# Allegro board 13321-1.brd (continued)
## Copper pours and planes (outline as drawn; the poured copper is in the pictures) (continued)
HDMI_PLL_GND on TOP: 16.76,74.9 16.64,75.02 16.64,75.41 16.76,75.53 17.4,75.53 18.44,76.57 18.44,83.46 18.52,83.53 19.18,83.53 19.56,83.15 19.56,75.15 19.3,74.9
HSIO_OUT on BOTTOM: 58.42,71.34 58.17,71.6 58.17,72.61 58.67,73.12 58.67,74.64 58.8,74.77 60.07,74.77 60.2,74.64 60.2,71.6 59.94,71.34
KB_BL_CTRL# on BOTTOM: 24.13,8.98 24,9.11 24,9.75 23.88,9.87 23.88,12.29 23.5,12.67 23.5,13.05 23.62,13.18 24.13,13.18 24.77,12.54 24.77,9.87 25.02,9.62 25.02,9.11 24.89,8.98
LCDVDD on TOP: 46.23,95.47 45.97,95.73 45.97,98.77 46.1,98.9 51.05,98.9 51.18,98.77 51.18,97.5 51.05,97.38 48.51,97.38 48.01,96.87 48.01,95.73 47.75,95.47 ; 4 cut-outs
LCDVDD on BOTTOM: 46.89,93.39 46.89,94.81 46.61,95.09 46.23,95.09 46.1,95.22 46.1,95.98 46.35,96.23 48.01,96.23 48.13,96.11 48.13,95.47 47.7,95.04 47.7,93.41 47.68,93.39 47.4,93.39 47.4,94.71 47.35,94.76 47.24,94.76 47.19,94.71 47.19,93.39
M_VREF_CA_DIMMA on TOP: 137.29,65.25 135.38,67.15 135.38,70.58 132.08,73.88 130.05,73.88 129.92,74.01 129.92,74.52 130.05,74.64 130.05,75.53 130.18,75.66 133.86,75.66 134.11,75.41 134.11,73.5 136.53,71.09 136.53,67.91 138.05,66.39 138.05,65.37 137.92,65.25 ; 4 cut-outs
M_VREF_CA_DIMMA on BOTTOM: 137.67,65.12 137.41,65.37 137.41,66.52 137.54,66.64 139.45,66.64 139.57,66.52 139.57,65.25 139.45,65.12 ; 2 cut-outs
M_VREF_DQ_DIMMA on TOP: 121.03,32.99 120.9,33.11 120.9,34.38 121.03,34.51 125.48,34.51 125.73,34.26 125.73,33.37 125.35,32.99 ; 6 cut-outs
PWR_1D35V on BOTTOM: 137.16,50.77 135.89,52.04 135.89,53.43 136.02,53.56 136.02,56.86 136.14,56.99 142.24,56.99 142.37,56.86 142.37,51.53 141.6,50.77 ; 2 cut-outs
PWR_1D35V_PHASE on BOTTOM: 139.06,44.93 139.06,46.07 138.56,46.58 138.56,48.86 138.68,48.99 140.72,48.99 140.84,48.86 140.84,46.7 140.34,46.2 140.34,44.93
PWR_3D3V_LL2 on BOTTOM: 35.05,75.91 34.8,76.17 34.8,79.85 35.05,80.1 39.24,80.1 39.37,79.98 39.37,76.93 39.24,76.8 38.1,76.8 37.72,76.42 37.72,76.04 37.59,75.91
PWR_5V_LL1 on BOTTOM: 26.8,75.91 26.54,76.17 26.54,79.72 26.8,79.98 30.1,79.98 30.23,79.85 30.23,76.42 29.72,75.91
PWR_CHG_PHASE on BOTTOM: 57.53,23.84 56.26,25.11 56.26,26.13 55.88,26.51 50.55,26.51 50.55,29.43 55.75,29.43 57.15,30.83 60.2,30.83 61.47,29.56 61.47,24.22 61.09,23.84
PWR_DCBATOUT_1D35V on BOTTOM: 139.45,39.46 139.32,39.59 139.32,42 139.06,42.26 139.06,43.78 141.1,43.78 141.48,43.4 141.48,43.02 141.6,42.89 142.37,42.89 142.88,42.39 144.27,42.39 144.4,42.26 144.4,41.24 142.62,39.46 ; 2 cut-outs
PWR_VCC_VSW1 on BOTTOM: 48.26,63.21 48.01,63.47 48.01,66.9 48.77,67.66 48.77,69.06 48.9,69.18 49.66,69.18 50.04,69.56 50.04,71.34 50.16,71.47 52.32,71.47 52.32,69.69 53.09,68.93 53.09,63.59 52.7,63.21
RING2 on BOTTOM: 16.89,21.94 16.76,22.07 16.76,23.97 17.65,24.86 17.65,28.29 17.78,28.42 18.67,28.42 18.92,28.16 18.92,24.22 18.03,23.34 18.03,22.07 17.91,21.94 ; 2 cut-outs
SLEEVE on TOP: 18.54,33.24 18.41,33.37 18.41,34 18.29,34.13 18.29,35.15 18.41,35.27 19.05,35.27 19.3,35.02 19.3,34.26 19.43,34.13 20.07,34.13 20.19,34 20.19,33.37 20.07,33.24 ; 1 cut-out
TP_VDD on TOP: 117.22,25.11 117.09,25.24 117.09,26.64 116.71,27.02 112.39,27.02 112.27,27.15 112.27,28.03 112.01,28.29 112.01,29.05 112.14,29.18 113.16,29.18 113.28,29.05 116.84,29.05 118.49,27.4 118.49,25.24 118.36,25.11 ; 3 cut-outs
TP_VDD on BOTTOM: 109.86,21.05 106.93,23.97 104.78,23.97 104.65,24.1 104.65,25.49 104.9,25.75 107.44,25.75 107.82,25.37 107.82,25.24 110.74,22.32 116.2,22.32 116.46,22.57 116.46,22.95 116.97,23.46 116.97,25.49 117.22,25.75 118.24,25.75 119.25,24.73 119.25,22.07 118.24,21.05 ; 2 cut-outs
TPAN_VDD on TOP: 28.96,94.71 28.83,94.84 28.83,95.85 29.08,96.11 30.48,96.11 32.26,97.88 32.26,99.92 32.38,100.04 34.04,100.04 34.16,99.92 34.16,96.36 33.91,96.11 32,96.11 31.75,95.85 31.75,94.84 31.62,94.71 ; 1 cut-out
TPAN_VDD on BOTTOM: 28.19,94.71 28.07,94.84 28.07,96.49 28.57,97 30.15,97 30.73,96.41 31.75,96.41 31.75,96.08 30.78,96.08 30.58,95.88 30.58,95.07 30.23,94.71
USB30_VCCA on BOTTOM: 26.16,55.47 26.16,59.4 24.77,60.8 24.77,64.99 24,65.75 14.73,65.75 14.22,66.26 14.22,67.4 14.61,67.79 25.27,67.79 27.05,66.01 27.05,61.69 28.32,60.42 28.32,56.23 27.56,55.47 ; 4 cut-outs
USB30_VCCB on BOTTOM: 20.07,47.21 19.56,47.72 15.88,47.72 15.37,48.23 15.37,49.88 15.75,50.26 21.46,50.26 22.48,49.24 24.38,49.24 24.38,47.97 24.26,47.85 22.73,47.85 22.1,47.21 ; 4 cut-outs

Small or netless copper shapes (teardrops, artwork), in the pictures only: 2 on TOP, 1 on BOTTOM

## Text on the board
Ref Des/Silkscreen Bottom: X1801:24MHZ | F6201:.5A/6V | F5204:1.1A/6V | F5202:.5A/6V | X1901:32.768KHZ
User.Comments: IVY_0913 | SAMPINTO | BAKAKAY
Ref Des/Silkscreen Top: F5203:1.1A/24V | F5401:1.1A/6V | F5201:1.1A/24V | X6601:12MHZ | PWR:8X6G1 | Cottonwood MB | 13321-1 | REV:A00 | MADE IN TAIWAN
User.27: Board Accuracy Check,Jun 11 16:07:18 2014,Passed | Dummy-Static-No Shape On Layer Check,Jun 11 16:07:19 2014,Passed | Split Plane Check,Mar 06 15:28:04 2014,Passed | TP Violations Check,Oct 23 11:41:53 2013,729 errors | Via On Moat Check,Oct 21 14:33:23 2013,117 errors
User.28: HEADER:Board Accuracy Check:1=show;2=show;3=show | HEADER:Dummy-Static-No Shape On Layer Check:1=show;2=hide;3=show;4=hide;5=show;6=show;7=show | HEADER:Split Plane Check:1=show;2=hide;3=show;4=hide;5=show;6=show;7=show
User.30: ByImpedance:100.0@_REF_L1=("4.0/10.0(L1)")|_REF_L6=("4.0/10.0(L6)")|Type="DP"|_REF_L4=("4.0/9.0(L4)")|_REF_L3=("4.0/9.0(L3)")|imp="100.0" | ByImpedance:110.0@Type="DP"|_REF_L4=("3.5/13.0(L4)")|_REF_L3=("3.5/13.0(L3)")|imp="110.0" | ByImpedance:37.5@_REF_L1=("8.0(L1)")|_REF_L6=("8.0(L6)")|Type="SE"|_REF_L4=("9.5(L4)")|_REF_L3=("9.5(L3)")|imp="37.5" | ByImpedance:40.0@_REF_L1=("7.0(L1)")|_REF_L6=("7.0(L6)")|Type="SE"|_REF_L4=("8.0(L4)")|_REF_L3=("8.0(L3)")|imp="40.0" | ByImpedance:45.0@_REF_L1=("5.5(L1)")|_REF_L6=("5.5(L6)")|Type="SE"|_REF_L4=("6.5(L4)")|_REF_L3=("6.5(L3)")|imp="45.0" | ByImpedance:48.0@_REF_L1=("5.0(L1)")|_REF_L6=("5.0(L6)")|Type="SE"|_REF_L4=("6.0(L4)")|_REF_L3=("6.0(L3)")|imp="48.0" | ByImpedance:50.0@_REF_L1=("4.5(L1)")|_REF_L6=("4.5(L6)")|Type="SE"|_REF_L4=("5.0(L4)")|_REF_L3=("5.0(L3)")|imp="50.0" | ByImpedance:55.0@_REF_L1=("3.5(L1)")|_REF_L6=("3.5(L6)")|Type="SE"|_REF_L4=("4.0(L4)")|_REF_L3=("4.0(L3)")|imp="55.0" | ByImpedance:70.0@_REF_L1=("7.0/5.0(L1)")|_REF_L6=("7.0/5.0(L6)")|Type="DP"|_REF_L4=("8.0/5.0(L4)")|_REF_L3=("8.0/5.0(L3)")|imp="70.0" | ByImpedance:80.0@_REF_L1=("5.5/5.0(L1)")|_REF_L6=("5.5/5.0(L6)")|Type="DP"|_REF_L4=("5.5/5.0(L4)" "6.0/6.0(L4)" "5.0/4.0(L4)")|_REF_L3=("5.5/5.0(L3)" "6.0/6.0(L3)" "5.0/4.0(L3)")|imp="80.0" | ByImpedance:85.0@_REF_L1=("4.0/4.0(L1)" "5.0/6.0(L1)")|_REF_L6=("4.0/4.0(L6)" "5.0/6.0(L6)")|Type="DP"|_REF_L4=("5.5/7.0(L4)" "5.0/5.5(L4)" "4.5/4.5(L4)")|_REF_L3=("5.5/7.0(L3)" "5.0/5.5(L3)" "4.5/4.5(L3)")|imp="85.0" | ByImpedance:90.0@_REF_L1=("4.0/5.0(L1)")|_REF_L6=("4.0/5.0(L6)")|Type="DP"|_REF_L4=("5.0/8.0(L4)" "4.0/5.0(L4)" "4.5/6.0(L4)")|_REF_L3=("5.0/8.0(L3)" "4.0/5.0(L3)" "4.5/6.0(L3)")|imp="90.0" | ByImpedance:95.0@_REF_L1=("4.0/6.5(L1)")|_REF_L6=("4.0/6.5(L6)")|Type="DP"|_REF_L4=("4.0/6.5(L4)")|_REF_L3=("4.0/6.5(L3)")|imp="95.0" | LayerIndex:nil | Source:6-1.2-10.xls | artWorks:("_REF_L3" "_REF_L4" "_REF_L6" "_REF_L1") | gtImpOutlineUsed:BOARD GEOMETRY/PANEL_OUTLINE
User.31: 0 | 16 | 51 | 59 | 47 | 39 | 63 | 20
User.32: 8 | 118 | 126 | 181 | 161 | 59 | 49 | 79
User.33: AUD_AGND | 5V_S5 | 5V_S0 | GND | 3D3V_S0 | DCBATOUT | VCC_CORE | 1D05V_S0
User.34: AUD_AGND | GND
User.37: This gerber is just for your reference to find the DP impedance traces in layer L1. | DP IMPEDANCE TABLE: L1 | * - Denotes that WIDTH | is NOT used in this layer | inside board outline. | IMP(Ohm) | 70.0 | 80.0 | 85.0 | 90.0 | 95.0 | 100.0 | WIDTH(mils) | *7.0/5.0 | *5.5/5.0 | 4.0/4.0 | *5.0/6.0 | *4.0/5.0 | *4.0/6.5 | *4.0/10.0 | TYPE | DP
User.39: This gerber is just for your reference to find the SE impedance traces in layer L1. | SE IMPEDANCE TABLE: L1 | * - Denotes that WIDTH | is NOT used in this layer | inside board outline. | IMP(Ohm) | 37.5 | 40.0 | 45.0 | 48.0 | 50.0 | 55.0 | WIDTH(mils) | 8.0 | *7.0 | *5.5 | *5.0 | 4.5 | *3.5 | TYPE | SE
User.41: This gerber is just for your reference to find the DP impedance traces in layer L3. | DP IMPEDANCE TABLE: L3 | * - Denotes that WIDTH | is NOT used in this layer | inside board outline. | IMP(Ohm) | 70.0 | 80.0 | 85.0 | 90.0 | 95.0 | 100.0 | 110.0 | WIDTH(mils) | *8.0/5.0 | *5.5/5.0 | *6.0/6.0 | *5.0/4.0 | *5.5/7.0 | *5.0/5.5 | 4.5/4.5 | *5.0/8.0 | *4.0/5.0 | *4.5/6.0 | *4.0/6.5 | *4.0/9.0 | *3.5/13.0 | TYPE | DP
User.43: This gerber is just for your reference to find the SE impedance traces in layer L3. | SE IMPEDANCE TABLE: L3 | * - Denotes that WIDTH | is NOT used in this layer | inside board outline. | IMP(Ohm) | 37.5 | 40.0 | 45.0 | 48.0 | 50.0 | 55.0 | WIDTH(mils) | *9.5 | 8.0 | *6.5 | 6.0 | 5.0 | 4.0 | TYPE | SE
User.45: This gerber is just for you reference to find the differential traces in layer BOTTOM | This gerber is just for you reference to find the differential traces in layer L3 | This gerber is just for you reference to find the differential traces in layer L4 | This gerber is just for you reference to find the differential traces in layer TOP | Note:Refer to DRILL layer for ELLIPSE drill direction | FIGURE | SIZE | 10.0 | 16.0 | 20.0 | 28.0 | 32.0 | 40.0 | 125.0 | 178.0 | 229.0 | 38.0 | 44.0 | 63.0 | 86.0 | 103.0 | 158.0 | 48.0x28.0 | 60.0x24.0 | 79.0x28.0 | 93.0x32.0 | 95.0x28.0 | 103.0x28.0 | 106.0x28.0 | 126.0x102.0 | DRILL CHART: TOP to BOTTOM | ALL UNITS ARE IN MILS | PLATED | NON-PLATED | QTY | 2251 | 425 | 19 | 10 | 9 | 8 | 3 | 4 | 1 | 2 | 7 | This gerber is just for your reference to find the DP impedance traces in layer L4. | This gerber is just for your reference to find the DP impedance traces in layer L6. | This gerber is just for your reference to find the SE impedance traces in layer L4. | This gerber is just for your reference to find the SE impedance traces in layer L6. | DP IMPEDANCE TABLE: L4 | DP IMPEDANCE TABLE: L6 | SE IMPEDANCE TABLE: L4 | SE IMPEDANCE TABLE: L6 | * - Denotes that WIDTH | is NOT used in this layer | inside board outline. | Model | Cottonwood MB | PCB_NO | 13321 | VER. | Layer | DRILL | L1 | L2VCC | L3 | TMASK | TPLACE | TSILK | TSMD | Designer | AKIM | IMP(Ohm) | 37.5 | 70.0 | 80.0 | 45.0 | 85.0 | 48.0 | 50.0 | 90.0 | 55.0 | 95.0 | 100.0 | 110.0 | Date | 06/11/2014 | WIDTH(mils) | *9.5 | 8.0 | 7.0 | *5.5 | *6.5 | 5.0 | 6.0 | 4.5 | 3.5 | 4.0 | *7.0/5.0 | *8.0/5.0 | *5.5/5.0 | *6.0/6.0 | 4.0/4.0 | *5.0/4.0 | *5.0/6.0 | *5.5/7.0 | 4.0/5.0 | *4.0/6.5 | *5.0/5.5 | *4.0/10.0 | 4.5/4.5 | *5.0/8.0 | *4.5/6.0 | *4.0/9.0 | *3.5/13.0 | TYPE | SE | DP | BMASK | BPLACE | BSILK | BSMD | L4 | L5GND | L6
